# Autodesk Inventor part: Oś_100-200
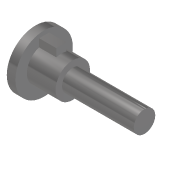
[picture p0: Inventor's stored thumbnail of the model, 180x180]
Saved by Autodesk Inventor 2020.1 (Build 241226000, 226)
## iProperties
Created: 2010-12
Part Number: Oś_100-200
Document SubType Name: Modeling
Designer: F.Stasiak
Density: 1 g/cm^3
Material: Ogólny
Appearance: Nierdzewny — matowy
Manager: www.cadconsulting.pl
Company: Fabian Stasiak CAD Consulting
Author: F.Stasiak
Subject: Zbiór ćwiczeń. Autodesk Inventor 2020. Kurs podstawowy
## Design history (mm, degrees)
sketch "Szkic1"
  geometry: C1 r 6 at (0, 0); 1 further point
  constraints: 1 centre point, 1 coincident
  dimensions: "d0" = 12 diameter of C1
extrude "Wyciągnięcie proste1" new body sketch "Szkic1" distance "d1" = 10; taper "d2" = 0 deg
sketch "Szkic2"
  geometry: C1 r 6 at (0, 0) reference; C2 r 10 at (0, 0)
  constraints: 1 centre point, 1 coincident
  dimensions: "d3" = 20 diameter of C2
extrude "Wyciągnięcie proste2" join sketch "Szkic2" distance "d4" = 3; taper "d5" = 0 deg
sketch "Szkic3"
  geometry: C1 r 6 at (0, 0) reference; C2 r 3.75 at (0, 0)
  constraints: 1 centre point, 1 coincident
  dimensions: "d6" = 7.5 diameter of C2
extrude "Wyciągnięcie proste3" join sketch "Szkic3" distance "d7" = 25; taper "d8" = 0 deg
sketch "Szkic4"
  geometry: L1 (-1.75, 5.739)-(-1.75, 8.5); L2 (-1.75, 8.5)-(1.75, 8.5); L3 (1.75, 8.5)-(1.75, 5.739); C1 r 10 at (0, 0) reference; A1 r 6 centre (0, 0) between (-1.75, 5.739) and (1.75, 5.739) reference
  constraints: 6 end point, 2 parallel, 2 point on circle, 1 perpendicular, 1 vertical
  dimensions: "d13" = 3.5 distance of L1.end L2.end; "d14" = 8.5 distance from line of C1.centre L2
extrude "Wyciągnięcie proste4" join sketch "Szkic4" distance "d15" = 6; taper "d16" = 0 deg
node "Bryła1"
